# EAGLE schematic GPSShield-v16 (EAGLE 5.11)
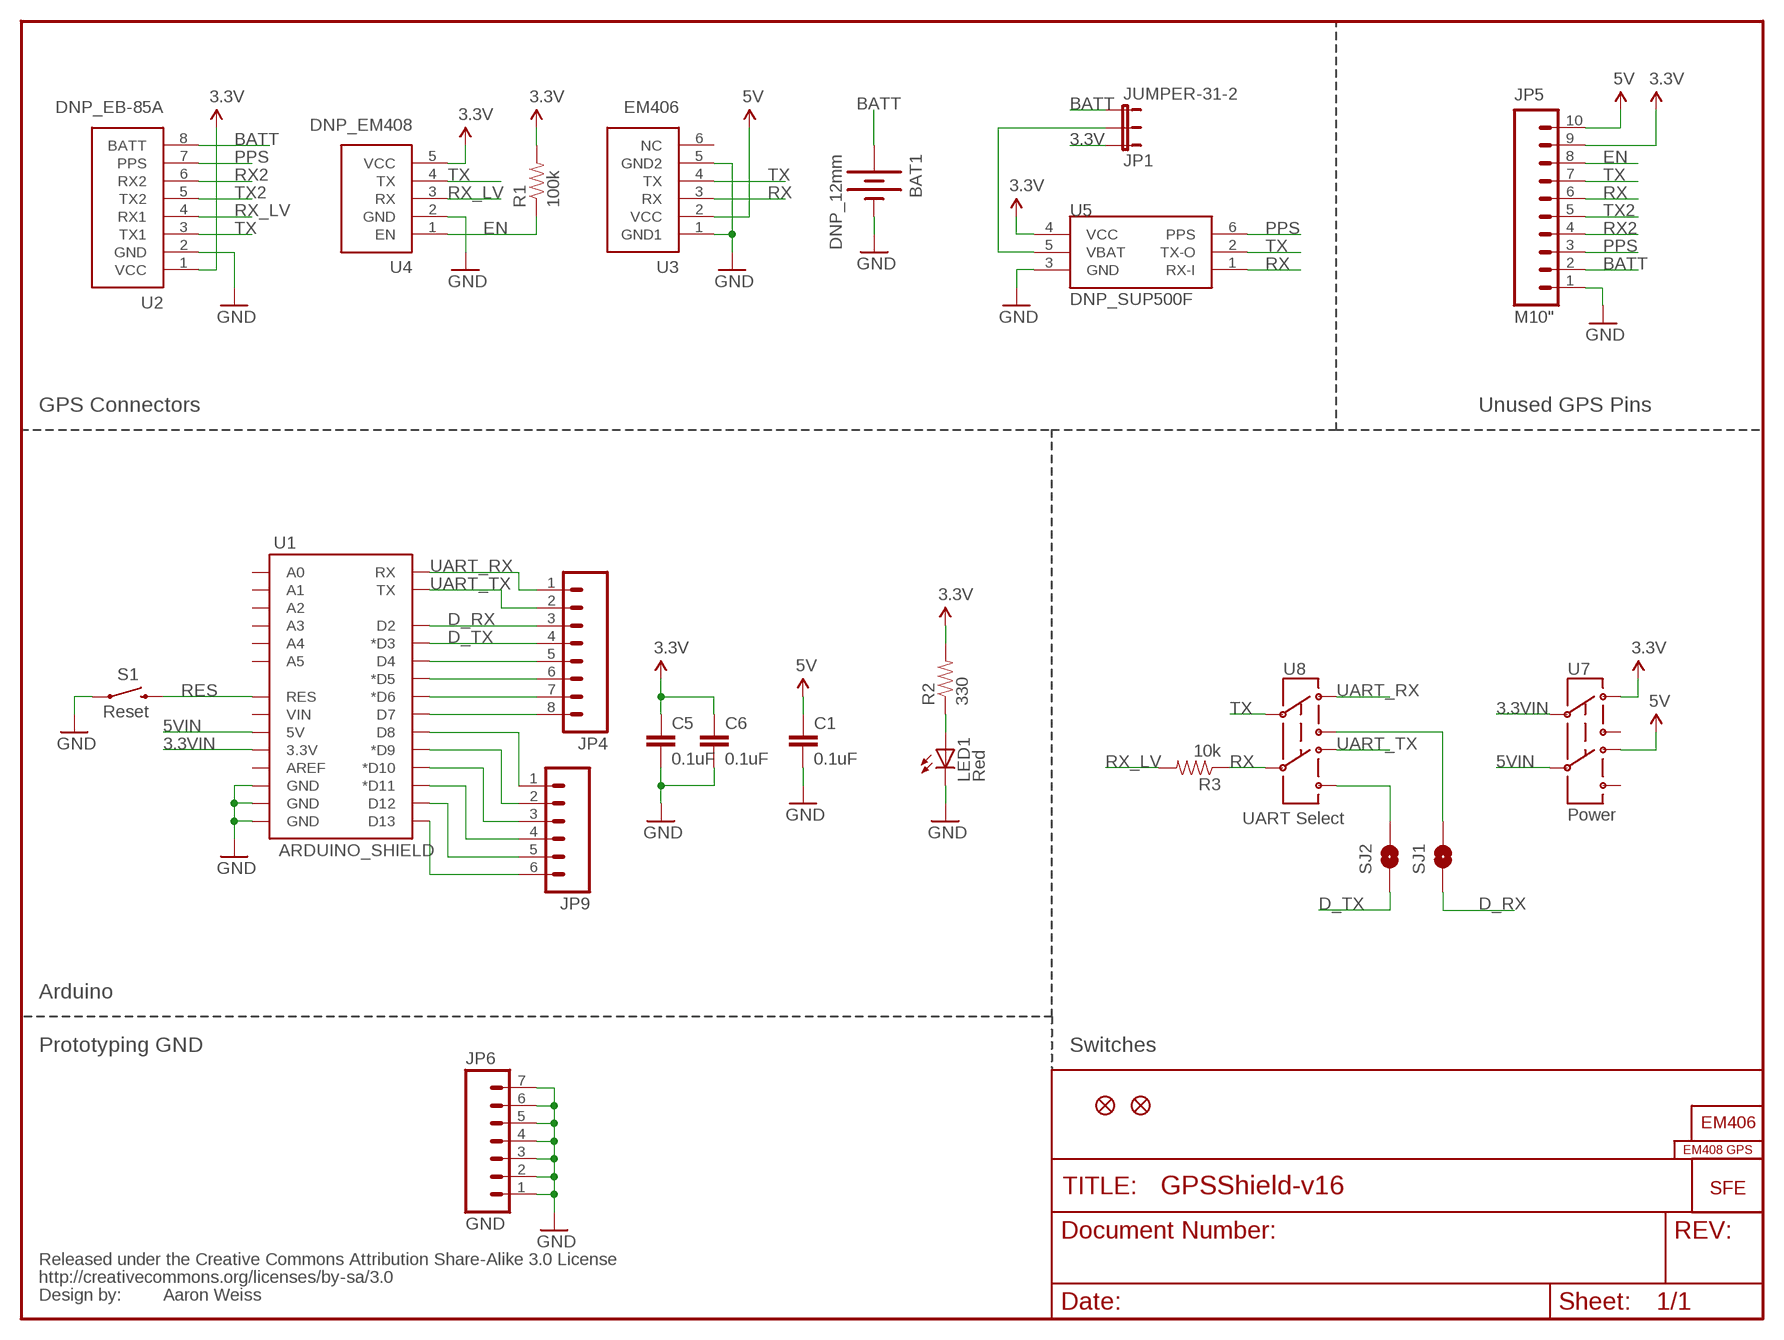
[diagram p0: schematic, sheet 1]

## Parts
BAT1  DNP_12mm  BATTERY12MM  [BATTCON_12MM]
C1  0.1uF  CAP0402-CAP  [0402-CAP]
C5  0.1uF  CAP0402-CAP  [0402-CAP]
C6  0.1uF  CAP0402-CAP  [0402-CAP]
JP1  JUMPER-31-2  [SJ_3_PASTE1&2]
JP3  LOGO-SFENEW  [SFE-NEW-WEBLOGO]
JP4  M08  [1X08]
JP5  M10"  [1X10]
JP6  GND  M07  [1X07]
JP7  FIDUCIAL1X2  [FIDUCIAL-1X2]
JP8  FIDUCIAL1X2  [FIDUCIAL-1X2]
JP9  M06SIP  [1X06]
LED1  Red  LED0603  [LED-0603]
R1  100k  RESISTOR0402-RES  [0402-RES]
R2  330  RESISTOR0402-RES  [0402-RES]
R3  10k  RESISTOR0402-RES  [0402-RES]
S1  Reset  SWITCH-MOMENTARY-2SMD  [TACTILE_SWITCH_SMD]
SJ1  D_RX  SOLDERJUMPERNC  [SJ_2S]
SJ2  D_TX  SOLDERJUMPERNC  [SJ_2S]
U1  ARDUINO_SHIELD  ARDUINO_SHIELDLABEL  [DUEMILANOVE_SHIELD]
U2  DNP_EB-85A  EB-85ASMD  [EB-85A]
U3  EM406  [EM406]
U4  DNP_EM408  EM408_CON  [EM408_CON]
U5  DNP_SUP500F  SUP500F  [SUP500F]
U7  Power  SWITCH-DPDTSMD  [AYZ0202]
U8  UART Select  SWITCH-DPDTSMD  [AYZ0202]
U$1  CREATIVE_COMMONS  [CREATIVE_COMMONS]
U$5  EM406_OUTLINE  [EM406_OUTLINE]
U$6  EM408_OUTLINE  [EM408_OUTLINE]

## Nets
3.3V: C5.1 C6.1 JP1.1 JP5.9 R1.2 R2.2 U2.1(VCC) U4.5(VCC) U5.4(VCC) U7.1
3.3VIN: U1.3.3V U7.2
5V: C1.1 JP5.10 U3.2(VCC) U7.4
5VIN: U1.5V U7.5
BATT: BAT1.PWR@1(+) JP1.3 JP5.2 U2.8(BATT)
D_RX: JP4.3 SJ1.1 U1.D2
D_TX: JP4.4 SJ2.1 U1.D3(*D3)
EN: JP5.8 R1.1 U4.1(EN)
GND: BAT1.GND(-) C1.2 C5.2 C6.2 JP5.1 JP6.1 JP6.2 JP6.3 JP6.4 JP6.5 JP6.6 JP6.7 LED1.C S1.1 U1.GND@0(GND) U1.GND@1(GND) U1.GND@2(GND) U2.2(GND) U3.1(GND1) U3.5(GND2) U4.2(GND) U5.3(GND)
N$1: LED1.A R2.1
N$111: JP4.5 U1.D4
N$112: JP4.6 U1.D5(*D5)
N$113: JP4.7 U1.D6(*D6)
N$114: JP4.8 U1.D7
N$115: JP9.1 U1.D8
N$116: JP9.2 U1.D9(*D9)
N$117: JP9.3 U1.D10(*D10)
N$118: JP9.4 U1.D11(*D11)
N$119: JP9.5 U1.D12
N$120: JP9.6 U1.D13
N$121: SJ2.2 U8.6
N$122: SJ1.2 U8.3
PPS: JP5.3 U2.7(PPS) U5.6(PPS)
RES: S1.3 U1.RES
RX: JP5.6 R3.1 U3.3(RX) U5.1(RX-I) U8.5
RX2: JP5.4 U2.6(RX2)
RX_LV: R3.2 U2.4(RX1) U4.3(RX)
TX: JP5.7 U2.3(TX1) U3.4(TX) U4.4(TX) U5.2(TX-O) U8.2
TX2: JP5.5 U2.5(TX2)
UART_RX: JP4.1 U1.RX U8.1
UART_TX: JP4.2 U1.TX U8.4
VBATT: JP1.2 U5.5(VBAT)
Unconnected: U1.A0 U1.A1 U1.A2 U1.A3 U1.A4 U1.A5 U1.AREF U1.VIN U3.6(NC) U7.3 U7.6

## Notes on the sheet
- GPS Connectors | Unused GPS Pins
- Arduino
- Prototyping GND | Switches
- Aaron Weiss

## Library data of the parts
BAT1 = SparkFun:BATTERY: Battery Holders
C1 C5 C6 = SparkFun:CAP: Capacitor
JP1 = SparkFun:JUMPER-3
JP3 = SparkFun:LOGO-SFE: Spark Fun Electronics PCB Logo
JP4 = SparkFun:M08: Header 8 Standard 8-pin 0.1" header. Use with straight break away headers (SKU : PRT-00116), right angle break away headers (PRT-00553), swiss pins (PRT-00743), machine pins (PRT-00117), and female headers (PRT-00115).
JP5 = SparkFun:M10: Header 10 Standard 10-pin 0.1" header. Use with straight break away headers (SKU : PRT-00116), right angle break away headers (PRT-00553), swiss pins (PRT-00743), machine pins (PRT-00117), and female headers (PRT-00115).
JP6 = SparkFun:M07: Header 7 Standard 7-pin 0.1" header. Use with straight break away headers (SKU : PRT-00116), right angle break away headers (PRT-00553), swiss pins (PRT-00743), machine pins (PRT-00117), and female headers (PRT-00115). NOTES ON THE VARIANTS LOCK and LOCK_LONGPADS... This footprint was designed to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
JP7 JP8 = SparkFun:FIDUCIAL: Fiducial Alignment Points
JP9 = SparkFun:M06: Header 6 Standard 6-pin 0.1" header. Use with straight break away headers (SKU : PRT-00116), right angle break away headers (PRT-00553), swiss pins (PRT-00743), machine pins (PRT-00117), and female headers (PRT-00115). Molex polarized connector foot print use with SKU : PRT-08094 with associated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
LED1 = SparkFun:LED: LEDs
R1-R3 = SparkFun:RESISTOR: Resistor
S1 = SparkFun:SWITCH-MOMENTARY-2
SJ1 SJ2 = SparkFun:SOLDERJUMPER: Solder Jumper
U1 = SparkFun:ARDUINO_SHIELD
U2 = SparkFun:EB-85A: EB-85A Connector Proven layout and schematic for ETek 5Hz GPS receiver connector. Spark Fun Electronics SKU : GPS-08297
U3 = SparkFun:EM406: EM406 Connector Proven layout and schematic for EM406 connector. Spark Fun Electronics SKU : GPS-00579
U4 = SparkFun:EM408_CON: This is the mating connector for the EM408 GPS receiver. The EM408 connects to the board via a cable, this connector footprint does not include the outline of the receiver. You should include the "EM408_Outline" device in your schematic if you are to use the EM408 in your design.
U5 = SparkFun:SUP500F: SUP500F Venus GPS
U7 U8 = SparkFun:SWITCH-DPDT: DPDT Version of the COM-00597
U$1 = SparkFun:CREATIVE_COMMONS
U$5 = SparkFun:EM406_OUTLINE
U$6 = SparkFun:EM408_OUTLINE: This device is only the outline of the EM408 GPS receiver. The device is intended to give the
